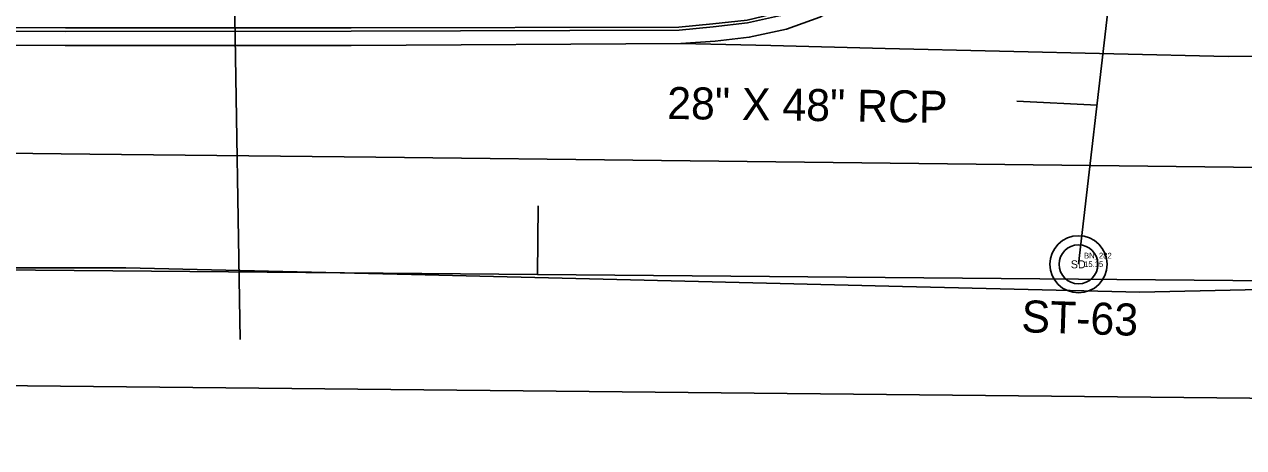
# Model space of a CAD drawing. Extents: x 509744 to 512285, y 1314862 to 1316822.
# Drawn here: x 511322.6 to 511429.2, y 1315604.3 to 1315641.3 of the extents above; entities that cross this region are included whole.
import ezdxf

# ---------------------------------------------------------------- set-up
doc = ezdxf.new("R2010")
doc.units = 0
for name, color, linetype in [('BaselineSurvey', 7, 'Continuous'), ('CGep_ep', 7, 'Continuous'), ('CGFace_ep', 7, 'Continuous'), ('LaneLine_ep', 7, 'Continuous'), ('ManholeSW_ep', 7, 'Continuous'), ('NonPlottingEle_dp', 7, 'Continuous'), ('PavtAsphalt_ep', 7, 'Continuous'), ('PavtAsphaltCrown_ep', 7, 'Continuous'), ('PavtBreak_ep', 7, 'Continuous'), ('PipeCulvert_ep', 7, 'Continuous'), ('SignTrussOH_ep', 7, 'Continuous'), ('TextElevLabel', 7, 'Continuous'), ('TextPtLabel', 7, 'Continuous')]:
    doc.layers.add(name, color=color, linetype=linetype)

msp = doc.modelspace()

# ---------------------------------------------------------------- linework, layer by layer
at = {"layer": 'BaselineSurvey'}
for p, q in [((511367.42, 1315619.41), (511367.47, 1315625.41)), ((511105.4, 1315621.62), (512116.98, 1315613.07))]:
    msp.add_line(p, q, dxfattribs=at)
at = {"layer": 'CGep_ep'}
msp.add_lwpolyline([(511408, 1315661.01), (511406.76, 1315658.27), (511404.5, 1315654.48), (511402.8, 1315652.01), (511401.53, 1315650.54), (511399.29, 1315648.45), (511396.96, 1315646.44), (511396.3, 1315646.09), (511394.21, 1315644.58), (511391.57, 1315643.12), (511388.66, 1315642.07), (511385.78, 1315641.41), (511382.8, 1315641.07), (511379.81, 1315640.79), (511351.14, 1315640.7), (511326.14, 1315640.67), (511301.14, 1315640.77)], dxfattribs=at)
at = {"layer": 'CGFace_ep'}
msp.add_lwpolyline([(511407.86, 1315687.32), (511408.85, 1315666.4), (511408.6, 1315663.98), (511407.76, 1315661.09), (511406.62, 1315658.31), (511404.38, 1315654.57), (511402.67, 1315652.1), (511401.4, 1315650.63), (511399.16, 1315648.55), (511396.83, 1315646.53), (511396.17, 1315646.18), (511394.1, 1315644.82), (511391.46, 1315643.37), (511388.55, 1315642.32), (511385.75, 1315641.67), (511382.77, 1315641.33), (511379.78, 1315641.04), (511351.14, 1315640.99), (511326.14, 1315640.98), (511301.14, 1315641.07), (511296.96, 1315641.13)], dxfattribs=at)
at = {"layer": 'LaneLine_ep'}
for points in [[(511453.27, 1315628.5), (511428.28, 1315628.79), (511403.28, 1315629.08), (511378.28, 1315629.37), (511353.28, 1315629.66), (511328.28, 1315629.95), (511303.28, 1315630.24), (511279.45, 1315630.63), (511260.69, 1315630.92)], [(512038.76, 1315604.27), (511985.06, 1315604.27), (511938.06, 1315604.59), (511812.25, 1315605.74), (511715.36, 1315606.17), (511673.64, 1315606.62), (511627.06, 1315607.12), (511592.81, 1315607.49), (511560.07, 1315607.84), (511514.08, 1315608.33), (511464.38, 1315608.25), (511259.26, 1315610.32)]]:
    msp.add_lwpolyline(points, dxfattribs=at)
at = {"layer": 'ManholeSW_ep'}
for radius in [2.5, 1.7]:
    msp.add_circle((511414.73, 1315620.3), radius, dxfattribs=at)
at = {"layer": 'NonPlottingEle_dp'}
msp.add_line((511409.34, 1315634.58), (511416.35, 1315634.22), dxfattribs=at)
at = {"layer": 'PavtAsphalt_ep'}
msp.add_lwpolyline([(511408.07, 1315687.33), (511409.03, 1315666.41), (511408.76, 1315663.92), (511408.43, 1315660.86), (511407.85, 1315657.89), (511405.5, 1315653.76), (511403.8, 1315651.28), (511402.53, 1315649.81), (511400.29, 1315647.73), (511397.96, 1315645.72), (511397.3, 1315645.37), (511394.74, 1315643.38), (511392.1, 1315641.93), (511389.19, 1315640.88), (511385.94, 1315640.16), (511382.96, 1315639.81), (511379.96, 1315639.61), (511351.13, 1315639.43), (511326.13, 1315639.45), (511301.13, 1315639.49)], dxfattribs=at)
at = {"layer": 'PavtAsphaltCrown_ep'}
msp.add_lwpolyline([(511247.8, 1315620), (511272.8, 1315620), (511289.61, 1315620), (511314.61, 1315620), (511331.42, 1315620), (511356.41, 1315619.4), (511374.35, 1315618.97), (511399.34, 1315618.37), (511420.1, 1315617.87), (511445.09, 1315618.43)], dxfattribs=at)
at = {"layer": 'PavtBreak_ep'}
msp.add_lwpolyline([(511453.14, 1315638.82), (511443.14, 1315638.68), (511433.14, 1315638.54), (511427.82, 1315638.47), (511417.82, 1315638.71), (511407.82, 1315638.95), (511397.82, 1315639.19), (511387.83, 1315639.43), (511379.96, 1315639.61)], dxfattribs=at)
at = {"layer": 'PipeCulvert_ep'}
msp.add_line((511420.86, 1315672.96), (511414.73, 1315620.3), dxfattribs=at)
at = {"layer": 'SignTrussOH_ep'}
msp.add_line((511340.85, 1315647.87), (511341.43, 1315613.71), dxfattribs=at)

# ---------------------------------------------------------------- texts
at = {"layer": 'ManholeSW_ep'}
msp.add_text('SD', height=0.7, dxfattribs=at).set_placement((511414.06, 1315619.95))
at = {"layer": 'NonPlottingEle_dp'}
for s, rotation, p in [('28" X 48" RCP', 359.1721, (511378.75, 1315633.02)), ('ST-63', 358.1578, (511409.71, 1315614.37))]:
    msp.add_text(s, height=2.8, rotation=rotation, dxfattribs=at).set_placement(p)
at = {"layer": 'TextElevLabel'}
msp.add_text('15.15', height=0.5, dxfattribs=at).set_placement((511415.22, 1315620.06))
at = {"layer": 'TextPtLabel'}
msp.add_text('BN_282', height=0.5, dxfattribs=at).set_placement((511415.22, 1315620.81))

doc.saveas('drawing.dxf')
